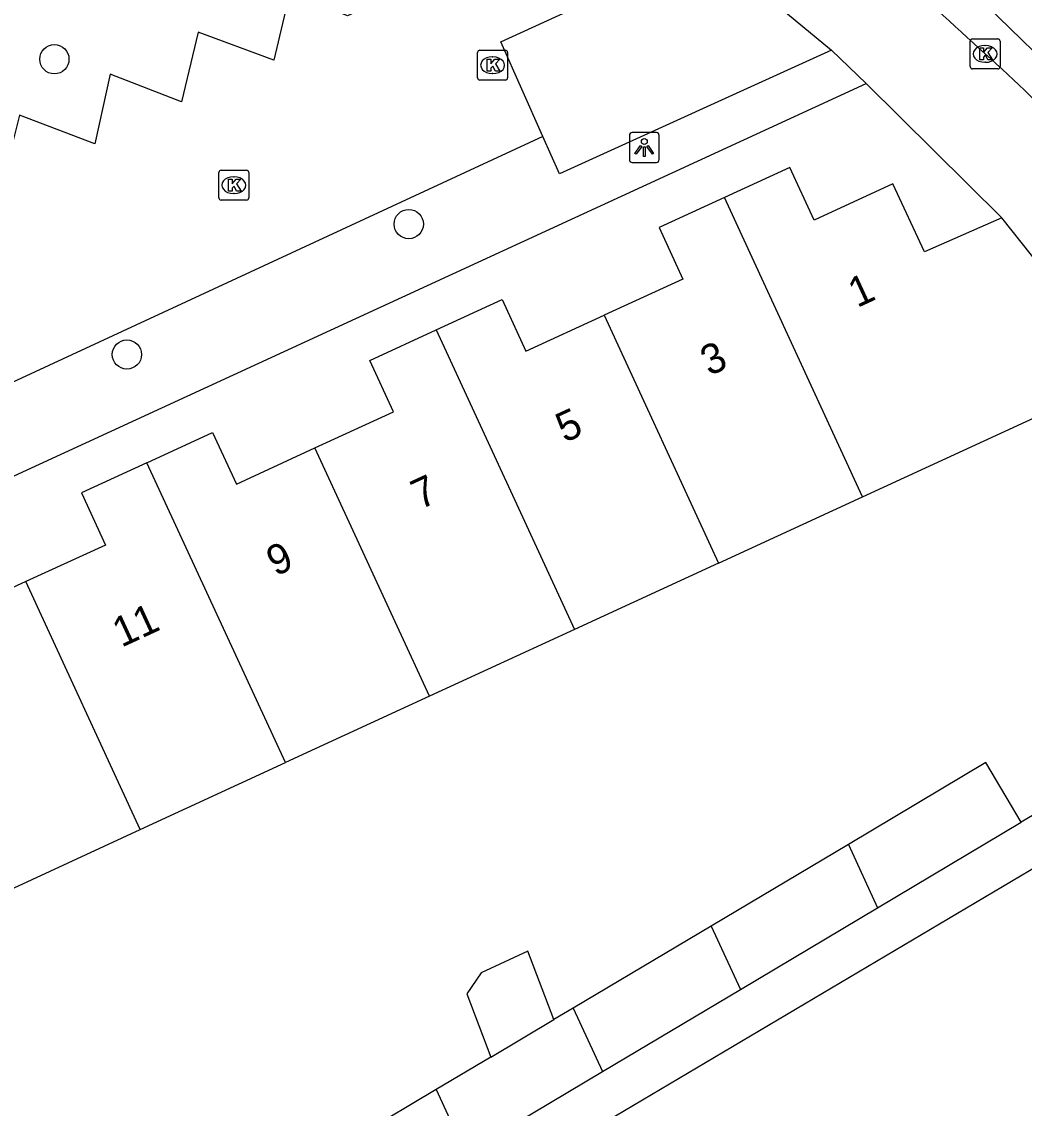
# Model space of a CAD drawing. Extents: x 159265 to 160143, y 383413 to 384319.
# Drawn here: x 159653.75 to 159687.28, y 383853.55 to 383889.92 of the extents above; entities that cross this region are included whole.
import ezdxf

# ---------------------------------------------------------------- set-up
doc = ezdxf.new("R2010")
doc.units = 0
for name, color, linetype in [('IMGEO_Boom', 7, 'Continuous'), ('IMGEO_Kolk', 7, 'Continuous'), ('IMGEO_Lichtpunt', 7, 'Continuous'), ('IMGEO_Pand', 7, 'Continuous'), ('IMGEO_Pand_nummerreeks', 7, 'Continuous'), ('IMGEO_Parkeervlak_open', 7, 'Continuous'), ('IMGEO_Rijbaan_lokaal_gesloten', 7, 'Continuous'), ('IMGEO_Voetpad_open', 7, 'Continuous')]:
    doc.layers.add(name, color=color, linetype=linetype)

msp = doc.modelspace()

# ---------------------------------------------------------------- linework, layer by layer
at = {"layer": 'IMGEO_Boom'}
for centre in [(159654.837, 383888.661), (159666.693, 383883.144), (159657.264, 383878.778)]:
    msp.add_circle(centre, 0.489, dxfattribs=at)
at = {"layer": 'IMGEO_Kolk'}
for p, q in [((159685.477, 383888.414), (159685.477, 383889.266)), ((159685.552, 383889.34), (159686.404, 383889.34)), ((159686.478, 383889.266), (159686.478, 383888.414)), ((159669.073, 383888.962), (159669.925, 383888.962)), ((159685.965, 383889.12), (159685.99, 383889.12)), ((159668.998, 383888.036), (159668.998, 383888.888)), ((159669.486, 383888.742), (159669.511, 383888.742)), ((159669.999, 383888.888), (159669.999, 383888.036)), ((159685.988, 383888.56), (159685.963, 383888.56)), ((159669.509, 383888.182), (159669.484, 383888.182)), ((159686.404, 383888.34), (159685.552, 383888.34)), ((159669.925, 383887.962), (159669.073, 383887.962)), ((159660.417, 383884.946), (159661.269, 383884.946)), ((159660.342, 383884.02), (159660.342, 383884.872)), ((159660.83, 383884.726), (159660.855, 383884.726)), ((159661.343, 383884.872), (159661.343, 383884.02)), ((159661.269, 383883.946), (159660.417, 383883.946)), ((159660.853, 383884.166), (159660.828, 383884.166))]:
    msp.add_line(p, q, dxfattribs=at)
for points in [[(159685.477, 383888.414), (159685.477, 383889.266)], [(159685.552, 383889.34), (159686.404, 383889.34)], [(159686.478, 383889.266), (159686.478, 383888.414)], [(159669.073, 383888.962), (159669.925, 383888.962)], [(159685.798, 383889.04), (159685.921, 383889.04), (159685.921, 383888.889), (159686.051, 383889.04), (159686.215, 383889.04), (159686.069, 383888.889), (159686.222, 383888.64), (159686.07, 383888.64), (159685.985, 383888.804), (159685.921, 383888.737), (159685.921, 383888.64), (159685.798, 383888.64), (159685.798, 383889.04)], [(159668.998, 383888.036), (159668.998, 383888.888)], [(159669.319, 383888.662), (159669.442, 383888.662), (159669.442, 383888.511), (159669.572, 383888.662), (159669.736, 383888.662), (159669.59, 383888.511), (159669.743, 383888.262), (159669.591, 383888.262), (159669.506, 383888.426), (159669.442, 383888.359), (159669.442, 383888.262), (159669.319, 383888.262), (159669.319, 383888.662)], [(159669.999, 383888.888), (159669.999, 383888.036)], [(159686.404, 383888.34), (159685.552, 383888.34)], [(159669.925, 383887.962), (159669.073, 383887.962)], [(159660.417, 383884.946), (159661.269, 383884.946)], [(159660.342, 383884.02), (159660.342, 383884.872)], [(159660.663, 383884.646), (159660.786, 383884.646), (159660.786, 383884.495), (159660.916, 383884.646), (159661.08, 383884.646), (159660.934, 383884.495), (159661.087, 383884.246), (159660.935, 383884.246), (159660.85, 383884.41), (159660.786, 383884.343), (159660.786, 383884.246), (159660.663, 383884.246), (159660.663, 383884.646)], [(159661.343, 383884.872), (159661.343, 383884.02)], [(159661.269, 383883.946), (159660.417, 383883.946)]]:
    msp.add_lwpolyline(points, dxfattribs=at)
for centre, start, end in [((159685.554, 383889.264), 91.552, 178.448), ((159685.554, 383889.264), 91.552, 178.448), ((159686.402, 383889.264), 1.552, 88.448), ((159686.402, 383889.264), 1.552, 88.448), ((159669.075, 383888.886), 91.552, 178.448), ((159669.075, 383888.886), 91.552, 178.448), ((159669.923, 383888.886), 1.552, 88.448), ((159669.923, 383888.886), 1.552, 88.448), ((159685.554, 383888.416), 181.552, 268.448), ((159685.554, 383888.416), 181.552, 268.448), ((159686.402, 383888.416), 271.552, 358.448), ((159686.402, 383888.416), 271.552, 358.448), ((159669.075, 383888.038), 181.552, 268.448), ((159669.075, 383888.038), 181.552, 268.448), ((159669.923, 383888.038), 271.552, 358.448), ((159669.923, 383888.038), 271.552, 358.448), ((159660.419, 383884.87), 91.552, 178.448), ((159660.419, 383884.87), 91.552, 178.448), ((159661.267, 383884.87), 1.552, 88.448), ((159661.267, 383884.87), 1.552, 88.448), ((159660.419, 383884.022), 181.552, 268.448), ((159660.419, 383884.022), 181.552, 268.448), ((159661.267, 383884.022), 271.552, 358.448), ((159661.267, 383884.022), 271.552, 358.448)]:
    msp.add_arc(centre, 0.0765, start, end, dxfattribs=at)
for centre, major_axis, ratio, start_param, end_param in [((159685.964, 383888.84), (-0.387, 0.002), 0.722429, 4.712389, 7.853982), ((159685.989, 383888.84), (-0.39, 0.002), 0.717154, 1.570796, 4.712389), ((159669.485, 383888.462), (-0.387, 0.002), 0.722429, 4.712389, 7.853982), ((159669.51, 383888.462), (-0.39, 0.002), 0.717154, 1.570796, 4.712389), ((159660.829, 383884.446), (-0.387, 0.002), 0.722429, 4.712389, 7.853982), ((159660.854, 383884.446), (-0.39, 0.002), 0.717154, 1.570796, 4.712389)]:
    msp.add_ellipse(centre, major_axis=major_axis, ratio=ratio, start_param=start_param, end_param=end_param, dxfattribs=at)
at = {"layer": 'IMGEO_Lichtpunt'}
for p, q in [((159674.075, 383886.11), (159674.075, 383885.303)), ((159674.075, 383886.11), (159674.075, 383885.303)), ((159674.977, 383886.205), (159674.169, 383886.205)), ((159674.977, 383886.205), (159674.169, 383886.205)), ((159675.071, 383885.303), (159675.071, 383886.11)), ((159675.071, 383885.303), (159675.071, 383886.11)), ((159674.169, 383885.209), (159674.977, 383885.209)), ((159674.169, 383885.209), (159674.977, 383885.209))]:
    msp.add_line(p, q, dxfattribs=at)
for points in [[(159674.449, 383885.774), (159674.488, 383885.746), (159674.3, 383885.484), (159674.262, 383885.511), (159674.449, 383885.774)], [(159674.551, 383885.726), (159674.598, 383885.726), (159674.598, 383885.404), (159674.551, 383885.404), (159674.551, 383885.726)], [(159674.661, 383885.746), (159674.699, 383885.773), (159674.886, 383885.511), (159674.847, 383885.483), (159674.661, 383885.746)]]:
    msp.add_lwpolyline(points, dxfattribs=at)
msp.add_circle((159674.574, 383885.908), 0.0994, dxfattribs=at)
for centre, start, end in [((159674.169, 383886.11), 90, 180), ((159674.169, 383886.11), 90, 180), ((159674.977, 383886.11), 0, 90), ((159674.977, 383886.11), 0, 90), ((159674.169, 383885.303), 180, 270), ((159674.169, 383885.303), 180, 270), ((159674.977, 383885.303), 270, 0), ((159674.977, 383885.303), 270, 360)]:
    msp.add_arc(centre, 0.0946, start, end, dxfattribs=at)
at = {"layer": 'IMGEO_Pand'}
for points in [[(159686.536, 383883.351), (159683.949, 383882.211), (159682.884, 383884.493), (159680.255, 383883.281), (159679.444, 383885.042), (159677.257, 383884.035)], [(159677.257, 383884.035), (159675.068, 383883.026), (159675.861, 383881.305), (159673.235, 383880.095)], [(159681.873, 383874.013), (159677.257, 383884.035)], [(159690.719, 383878.088), (159686.536, 383883.351)], [(159667.605, 383879.601), (159669.813, 383880.618), (159670.611, 383878.887), (159673.235, 383880.095)], [(159673.235, 383880.095), (159677.061, 383871.796)], [(159663.556, 383875.652), (159666.185, 383876.863), (159665.394, 383878.582), (159667.605, 383879.601)], [(159667.605, 383879.601), (159672.233, 383869.572)], [(159681.873, 383874.013), (159690.719, 383878.088)], [(159657.935, 383875.158), (159660.13, 383876.169), (159660.927, 383874.441), (159663.556, 383875.652)], [(159667.387, 383867.339), (159663.556, 383875.652)], [(159657.935, 383875.158), (159655.74, 383874.146), (159656.543, 383872.402), (159653.888, 383871.179)], [(159662.566, 383865.118), (159657.935, 383875.158)], [(159677.061, 383871.796), (159681.873, 383874.013)], [(159653.888, 383871.179), (159651.232, 383869.955), (159650.43, 383871.696), (159648.252, 383870.692)], [(159677.061, 383871.796), (159672.233, 383869.572)], [(159657.706, 383862.879), (159653.888, 383871.179)], [(159672.233, 383869.572), (159667.387, 383867.339)], [(159667.387, 383867.339), (159662.566, 383865.118)], [(159657.706, 383862.879), (159662.566, 383865.118)], [(159687.186, 383863.12), (159685.996, 383865.118), (159681.401, 383862.382)], [(159682.38, 383860.258), (159687.186, 383863.12)], [(159652.874, 383860.653), (159657.706, 383862.879)], [(159681.401, 383862.382), (159676.812, 383859.649)], [(159681.401, 383862.382), (159682.38, 383860.258)], [(159677.792, 383857.526), (159682.38, 383860.258)], [(159676.812, 383859.649), (159672.197, 383856.901)], [(159676.812, 383859.649), (159677.792, 383857.526)], [(159671.55, 383856.515), (159670.678, 383858.806), (159669.117, 383858.082), (159668.635, 383857.377), (159669.44, 383855.259)], [(159673.176, 383854.777), (159677.792, 383857.526)], [(159672.197, 383856.901), (159671.55, 383856.515)], [(159672.197, 383856.901), (159673.176, 383854.777)], [(159669.44, 383855.259), (159671.55, 383856.515)], [(159669.44, 383855.259), (159667.615, 383854.172)], [(159668.595, 383852.048), (159673.176, 383854.777)], [(159667.615, 383854.172), (159662.678, 383851.232)], [(159667.615, 383854.172), (159668.595, 383852.048)]]:
    msp.add_lwpolyline(points, dxfattribs=at)
at = {"layer": 'IMGEO_Parkeervlak_open'}
for points in [[(159671.184, 383886.075), (159669.778, 383889.25), (159676.673, 383892.409)], [(159668.962, 383892.09), (159664.647, 383890.115), (159662.717, 383890.902), (159662.185, 383888.626), (159659.643, 383889.566), (159659.09, 383887.239), (159656.708, 383888.161), (159656.196, 383885.826), (159653.674, 383886.785), (159653.102, 383884.519), (159650.579, 383885.52), (159650.088, 383883.154), (159647.555, 383884.164), (159647.035, 383881.668), (159644.651, 383882.77), (159644.1, 383880.363), (159641.678, 383881.265), (159641.115, 383878.998), (159638.603, 383879.948), (159638.444, 383880.008), (159636.763, 383875.546)]]:
    msp.add_lwpolyline(points, dxfattribs=at)
at = {"layer": 'IMGEO_Rijbaan_lokaal_gesloten'}
msp.add_lwpolyline([(159705.244, 383862.233), (159704.628, 383863.529), (159702.949, 383866.76), (159701.226, 383869.948), (159699.417, 383873.136), (159697.221, 383876.928), (159695.886, 383878.953), (159694.637, 383880.805), (159692.957, 383883.175), (159691.45, 383884.984), (159688.78, 383887.785), (159686.024, 383890.457), (159682.837, 383893.257), (159679.908, 383895.713), (159676.937, 383897.996), (159673.879, 383900.279), (159670.218, 383902.865), (159665.342, 383906.183)], dxfattribs=at)
for centre, radius, start, end in [((159570.762, 383764.124), 169.791, 47.26742, 50.20989), ((159655.614, 383854.807), 45.611, 37.9955, 48.2607)]:
    msp.add_arc(centre, radius, start, end, dxfattribs=at)
at = {"layer": 'IMGEO_Voetpad_open'}
for points in [[(159676.673, 383892.409), (159680.835, 383888.963)], [(159680.835, 383888.963), (159671.739, 383884.822), (159671.184, 383886.075)], [(159681.994, 383887.853), (159680.835, 383888.963)], [(159633.167, 383865.358), (159681.994, 383887.853)], [(159686.536, 383883.351), (159681.994, 383887.853)], [(159671.184, 383886.075), (159641.027, 383872.1)], [(159691.171, 383865.485), (159687.186, 383863.12)], [(159656.671, 383843.975), (159656.295, 383845.109), (159664.574, 383847.937), (159690.772, 383863.468)]]:
    msp.add_lwpolyline(points, dxfattribs=at)

# ---------------------------------------------------------------- texts
at = {"layer": 'IMGEO_Pand_nummerreeks'}
for s, p in [('1', (159681.694, 383880.33)), ('3', (159676.751, 383878.046)), ('5', (159671.912, 383875.81)), ('7', (159667.074, 383873.575)), ('9', (159662.235, 383871.339)), ('11', (159657.082, 383868.96))]:
    msp.add_text(s, height=1, rotation=24.7977, dxfattribs=at).set_placement(p)

doc.saveas('drawing.dxf')
